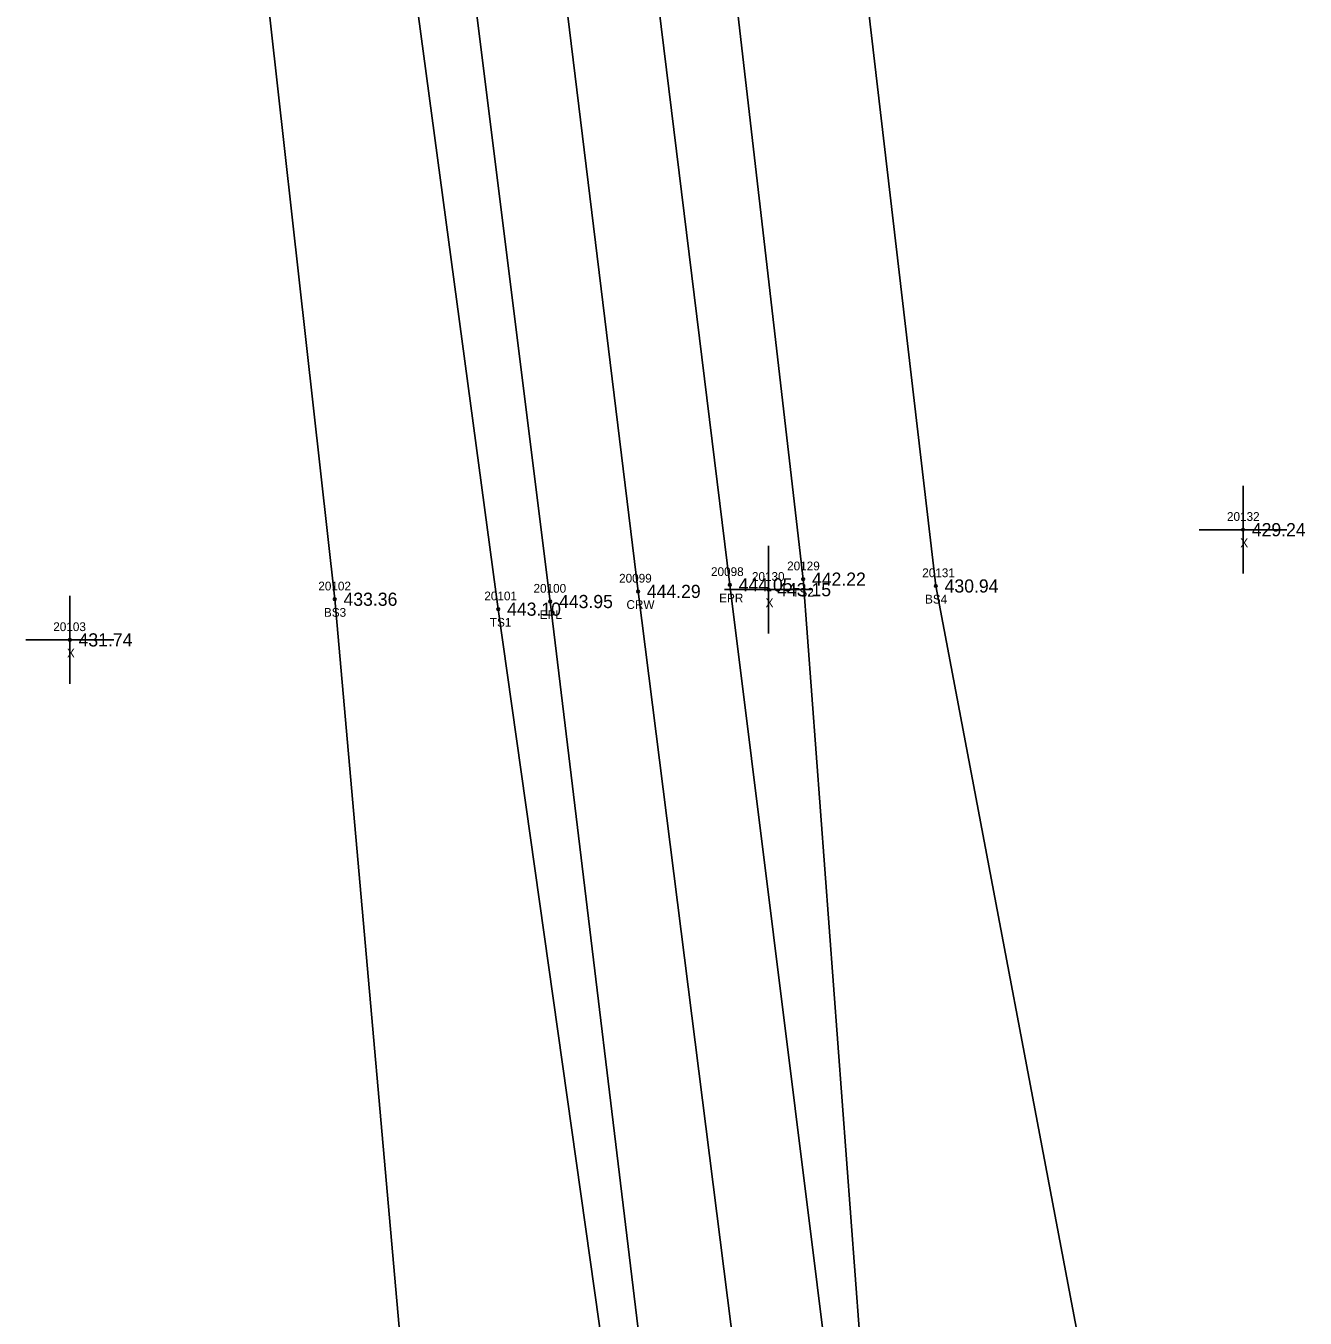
# Model space of a CAD drawing. Extents: x 1858461 to 1858936, y 1147060 to 1148183.
# Drawn here: x 1858572.1 to 1858717.9, y 1147876.4 to 1148023.6 of the extents above; entities that cross this region are included whole.
import ezdxf

# ---------------------------------------------------------------- set-up
doc = ezdxf.new("R2010")
doc.units = 0
for name, color, linetype in [('RD_DTM_BkLn1', 7, 'Continuous'), ('RD_DTM_BkLn2', 7, 'Continuous'), ('RD_DTM_BkLn_txCode', 7, 'Continuous'), ('RD_EX_Misc', 7, 'Continuous'), ('RD_EX_Misc_txCode', 7, 'Continuous'), ('RD_EX_Road', 7, 'Continuous'), ('RD_EX_Road_txCode', 7, 'Continuous'), ('RD_EX_TX_Misc_ELEV', 7, 'Continuous'), ('RD_EX_TX_Road_ELEV', 7, 'Continuous'), ('RD_HC_Survey_ELEV', 7, 'Continuous'), ('RD_HC_Survey_txCode', 7, 'Continuous'), ('RD_SMD_Locator', 7, 'Continuous')]:
    doc.layers.add(name, color=color, linetype=linetype)

msp = doc.modelspace()

# ---------------------------------------------------------------- linework, layer by layer
at = {"layer": 'RD_DTM_BkLn1'}
msp.add_lwpolyline([(1858679.02, 1147660.19), (1858666.85, 1147759.91), (1858654.47, 1147859.47), (1858641.87, 1147959.15), (1858630.02, 1148056.08), (1858617.26, 1148157.44)], dxfattribs=at)
at = {"layer": 'RD_DTM_BkLn2'}
for points in [[(1858693.62, 1147653.8), (1858703.51, 1147658.34), (1858709.65, 1147670.29), (1858700.15, 1147768.19), (1858693.67, 1147865.34), (1858675.79, 1147959.77), (1858663.27, 1148067), (1858650.31, 1148162.46)], [(1858691.24, 1147663), (1858693.74, 1147672.32), (1858681.4, 1147761.99), (1858668.07, 1147861.46), (1858660.68, 1147960.55), (1858649.11, 1148060.84), (1858635.41, 1148160.22)], [(1858665.51, 1147658.67), (1858661.09, 1147664.96), (1858652.2, 1147758.21), (1858640.05, 1147857.23), (1858625.95, 1147957.13), (1858612.72, 1148055.44), (1858600.29, 1148155.52)], [(1858693.62, 1147653.8), (1858663.6, 1147639.15), (1858647.78, 1147639.17), (1858628.12, 1147754.45), (1858616.79, 1147851.29), (1858607.32, 1147958.26), (1858596.73, 1148053.14), (1858583.42, 1148154.64)]]:
    msp.add_lwpolyline(points, dxfattribs=at)
at = {"layer": 'RD_EX_Misc'}
for p, q in [((1858710.78, 1147961.18), (1858710.78, 1147971.18)), ((1858705.78, 1147966.18), (1858715.78, 1147966.18)), ((1858656.72, 1147954.35), (1858656.72, 1147964.35)), ((1858651.72, 1147959.35), (1858661.72, 1147959.35)), ((1858577.14, 1147948.63), (1858577.14, 1147958.63)), ((1858572.14, 1147953.63), (1858582.14, 1147953.63))]:
    msp.add_line(p, q, dxfattribs=at)
at = {"layer": 'RD_EX_Road'}
for points in [[(1858679.02, 1147660.19), (1858688.73, 1147661.54), (1858677.21, 1147761.6), (1858664.75, 1147860.38), (1858652.33, 1147959.9), (1858640.18, 1148058.71), (1858627.63, 1148158.94)], [(1858679.02, 1147660.19), (1858669.49, 1147658.82), (1858657, 1147758.92), (1858643.96, 1147857.84), (1858631.87, 1147958), (1858619.69, 1148055.49), (1858606.59, 1148156.75)]]:
    msp.add_lwpolyline(points, dxfattribs=at)
at = {"layer": 'RD_SMD_Locator'}
for centre in [(1858710.78, 1147966.18), (1858652.33, 1147959.9), (1858656.72, 1147959.35), (1858660.68, 1147960.55), (1858675.79, 1147959.77), (1858607.32, 1147958.26), (1858631.87, 1147958), (1858641.87, 1147959.15), (1858625.95, 1147957.13), (1858577.14, 1147953.63)]:
    msp.add_circle(centre, 0.15, dxfattribs=at)

# ---------------------------------------------------------------- texts
at = {"layer": 'RD_DTM_BkLn_txCode'}
for s, p in [('20129', (1858658.85, 1147961.55)), ('20131', (1858674.24, 1147960.77)), ('20102', (1858605.45, 1147959.26)), ('TS2', (1858659.44, 1147958.55)), ('20101', (1858624.36, 1147958.13)), ('BS4', (1858674.56, 1147957.77)), ('BS3', (1858606.09, 1147956.26)), ('TS1', (1858624.99, 1147955.13))]:
    msp.add_text(s, height=1, dxfattribs=at).set_placement(p)
at = {"layer": 'RD_EX_Misc_txCode'}
for s, p in [('20132', (1858708.95, 1147967.18)), ('X', (1858710.47, 1147964.18)), ('20130', (1858654.84, 1147960.35)), ('X', (1858656.4, 1147957.35)), ('20103', (1858575.26, 1147954.63)), ('X', (1858576.82, 1147951.63))]:
    msp.add_text(s, height=1, dxfattribs=at).set_placement(p)
at = {"layer": 'RD_EX_Road_txCode'}
for s, p in [('20098', (1858650.18, 1147960.9)), ('20100', (1858629.96, 1147959)), ('EPR', (1858651.11, 1147957.9)), ('EPL', (1858630.67, 1147956))]:
    msp.add_text(s, height=1, dxfattribs=at).set_placement(p)
at = {"layer": 'RD_EX_TX_Misc_ELEV'}
for s, p in [('429.24', (1858711.78, 1147965.43)), ('442.22', (1858661.68, 1147959.8)), ('443.15', (1858657.72, 1147958.6)), ('430.94', (1858676.79, 1147959.02)), ('433.36', (1858608.32, 1147957.51)), ('443.10', (1858626.95, 1147956.38)), ('431.74', (1858578.14, 1147952.88))]:
    msp.add_text(s, height=1.5, dxfattribs=at).set_placement(p)
at = {"layer": 'RD_EX_TX_Road_ELEV'}
for s, p in [('444.05', (1858653.33, 1147959.15)), ('443.95', (1858632.87, 1147957.25))]:
    msp.add_text(s, height=1.5, dxfattribs=at).set_placement(p)
at = {"layer": 'RD_HC_Survey_ELEV'}
msp.add_text('444.29', height=1.5, dxfattribs=at).set_placement((1858642.87, 1147958.4))
at = {"layer": 'RD_HC_Survey_txCode'}
for s, p in [('20099', (1858639.71, 1147960.15)), ('CRW', (1858640.55, 1147957.15))]:
    msp.add_text(s, height=1, dxfattribs=at).set_placement(p)

doc.saveas('drawing.dxf')
